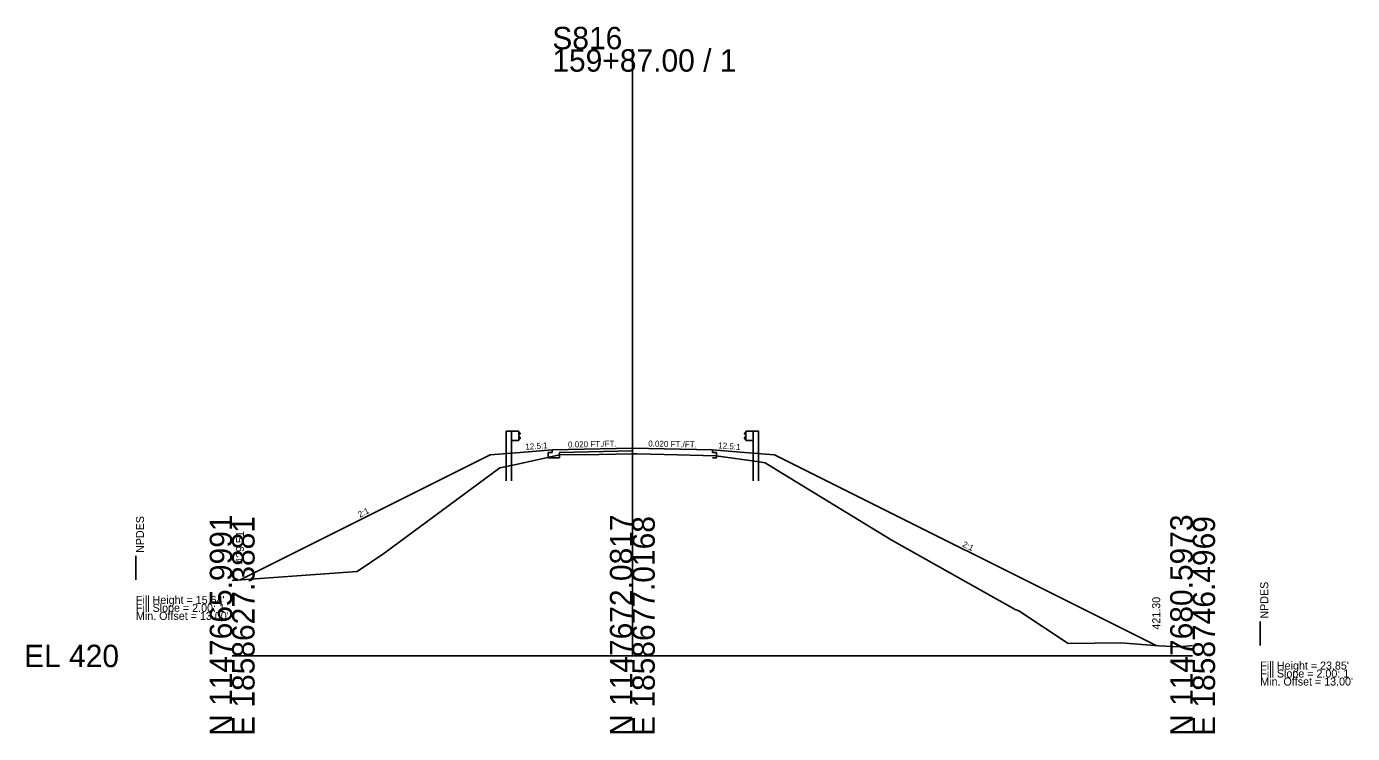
# Model space of a CAD drawing. Extents: x -76 to 4323, y -10 to 2055.
# Drawn here: x 3074.3 to 3240, y -9.7 to 78.7 of the extents above; entities that cross this region are included whole.
import ezdxf

# ---------------------------------------------------------------- set-up
doc = ezdxf.new("R2010")
doc.units = 0
for name, color, linetype in [('Default', 7, 'Continuous'), ('RD_GPK_XS_Cell', 7, 'Continuous'), ('RD_XS_Base', 7, 'Continuous'), ('RD_XS_Buildup', 7, 'Continuous'), ('RD_XS_EarthShd', 7, 'Continuous'), ('RD_XS_ExGround', 7, 'Continuous'), ('RD_XS_GR', 7, 'Continuous'), ('RD_XS_NPDES', 7, 'Continuous'), ('RD_XS_Pave', 7, 'Continuous'), ('RD_XS_TieSlope', 7, 'Continuous'), ('RD_XS_TX_Elev_PR', 7, 'Continuous'), ('RD_XS_TX_ShdSlope', 7, 'Continuous'), ('RD_XS_TX_Slope', 7, 'Continuous'), ('RD_XS_TX_Warning', 7, 'Continuous')]:
    doc.layers.add(name, color=color, linetype=linetype)

msp = doc.modelspace()

# ---------------------------------------------------------------- linework, layer by layer
at = {"layer": 'Default'}
for p, q in [((3140, 25.77), (3150, 25.97)), ((3150, 25.97), (3160, 25.77))]:
    msp.add_line(p, q, dxfattribs=at)
at = {"layer": 'RD_GPK_XS_Cell'}
for p, q in [((3150, 0), (3150, 75.84)), ((3100, 0), (3150, 0)), ((3150, 0), (3220, 0))]:
    msp.add_line(p, q, dxfattribs=at)
at = {"layer": 'RD_XS_Base'}
for p, q in [((3140.89, 24.78), (3140.89, 25.13)), ((3140, 24.77), (3140.89, 24.78))]:
    msp.add_line(p, q, dxfattribs=at)
at = {"layer": 'RD_XS_Buildup'}
for p, q in [((3140.89, 25.45), (3150, 25.64)), ((3140.89, 25.13), (3140.89, 25.45))]:
    msp.add_line(p, q, dxfattribs=at)
at = {"layer": 'RD_XS_EarthShd'}
for p, q in [((3136, 25.45), (3132.25, 25.15)), ((3140, 25.77), (3136, 25.45)), ((3160, 25.77), (3164, 25.45)), ((3164, 25.45), (3167.75, 25.15))]:
    msp.add_line(p, q, dxfattribs=at)
at = {"layer": 'RD_XS_ExGround'}
for p, q in [((3135.49, 23.95), (3140.89, 25.13)), ((3140.89, 25.13), (3145.84, 25.2)), ((3145.84, 25.2), (3150, 25.27)), ((3150, 25.27), (3150.54, 25.28)), ((3150.54, 25.28), (3155.66, 25.14)), ((3155.66, 25.14), (3160.43, 25.01)), ((3160.43, 25.01), (3165.89, 24.26)), ((3118.94, 12.8), (3133.46, 23.52)), ((3133.46, 23.52), (3135.49, 23.95)), ((3165.89, 24.26), (3166.6, 24.16)), ((3166.6, 24.16), (3168.01, 23.28)), ((3168.01, 23.28), (3182.32, 14.5)), ((3182.32, 14.5), (3197.84, 5.79)), ((3115.61, 10.55), (3118.94, 12.8)), ((3100, 9.44), (3115.61, 10.55)), ((3197.84, 5.79), (3198.28, 5.63)), ((3198.28, 5.63), (3204.43, 1.56)), ((3204.43, 1.56), (3211.04, 1.62)), ((3211.04, 1.62), (3215.78, 1.27)), ((3215.78, 1.27), (3218.37, 1.14)), ((3218.37, 1.14), (3220, 1.31))]:
    msp.add_line(p, q, dxfattribs=at)
at = {"layer": 'RD_XS_GR'}
for p, q in [((3134.25, 28.1), (3134.25, 25.31)), ((3134.92, 28.1), (3134.25, 28.1)), ((3134.92, 28.1), (3134.92, 25.36)), ((3135.83, 28.1), (3134.92, 28.1)), ((3135.83, 26.94), (3134.92, 26.94)), ((3135.83, 26.94), (3135.83, 28.1)), ((3135.83, 28.03), (3136, 27.83)), ((3136, 27.78), (3135.83, 27.58)), ((3136, 27.26), (3135.83, 27.46)), ((3135.83, 27.01), (3136, 27.21)), ((3136, 27.83), (3136, 27.78)), ((3136, 27.21), (3136, 27.26)), ((3164.17, 28.03), (3164, 27.83)), ((3164, 27.83), (3164, 27.78)), ((3164, 27.78), (3164.17, 27.58)), ((3164, 27.26), (3164.17, 27.46)), ((3164, 27.21), (3164, 27.26)), ((3164.17, 27.01), (3164, 27.21)), ((3164.17, 26.94), (3164.17, 28.1)), ((3164.17, 28.1), (3165.08, 28.1)), ((3164.17, 26.94), (3165.08, 26.94)), ((3165.08, 28.1), (3165.08, 25.36)), ((3165.08, 28.1), (3165.75, 28.1)), ((3165.75, 28.1), (3165.75, 25.31)), ((3134.25, 25.31), (3134.25, 21.89)), ((3134.92, 21.89), (3134.92, 25.36)), ((3165.08, 21.89), (3165.08, 25.36)), ((3165.75, 25.31), (3165.75, 21.89))]:
    msp.add_line(p, q, dxfattribs=at)
at = {"layer": 'RD_XS_NPDES'}
for p, q in [((3087.98, 9.51), (3087.98, 12.51)), ((3228.45, 1.3), (3228.45, 4.3))]:
    msp.add_line(p, q, dxfattribs=at)
at = {"layer": 'RD_XS_Pave'}
for p, q in [((3139.5, 25.43), (3140, 25.44)), ((3139.5, 24.76), (3139.5, 25.43)), ((3140, 25.44), (3140, 25.77)), ((3160, 25.44), (3160, 25.77)), ((3160.5, 25.43), (3160, 25.44)), ((3160.5, 24.76), (3160.5, 25.43)), ((3140, 24.77), (3139.5, 24.76)), ((3160, 24.77), (3160.5, 24.76))]:
    msp.add_line(p, q, dxfattribs=at)
at = {"layer": 'RD_XS_TieSlope'}
for p, q in [((3132.25, 25.15), (3100.98, 9.51)), ((3167.75, 25.15), (3215.45, 1.3))]:
    msp.add_line(p, q, dxfattribs=at)

# ---------------------------------------------------------------- texts
at = {"layer": 'RD_GPK_XS_Cell'}
for s, p in [('S816', (3140, 75.84)), ('159+87.00 / 1', (3140, 73.04)), ('EL 420', (3074, -1.4))]:
    msp.add_text(s, height=2.8, dxfattribs=at).set_placement(p)
for s, p in [('N 1147665.9991', (3100, -10)), ('E 1858627.3881', (3102.8, -10)), ('N 1147672.0817', (3150, -10)), ('E 1858677.0168', (3152.8, -10)), ('N 1147680.5973', (3220, -10)), ('E 1858746.4969', (3222.8, -10))]:
    msp.add_text(s, height=2.8, rotation=90, dxfattribs=at).set_placement(p)
at = {"layer": 'RD_XS_TX_Elev_PR'}
for s, p in [('429.51', (3101.48, 11.51)), ('421.30', (3215.95, 3.3))]:
    msp.add_text(s, height=1, rotation=90, dxfattribs=at).set_placement(p)
at = {"layer": 'RD_XS_TX_ShdSlope'}
for rotation, p in [(4.5739, (3136.66, 25.75)), (355.4261, (3160.7, 25.96))]:
    msp.add_text('12.5:1', height=0.75, rotation=rotation, dxfattribs=at).set_placement(p)
at = {"layer": 'RD_XS_TX_Slope'}
for s, rotation, p in [('0.020 FT./FT.', 1.1458, (3141.97, 26.05)), ('0.020 FT./FT.', 358.8542, (3151.98, 26.18)), ('2:1', 26.5651, (3115.95, 17.28)), ('2:1', 333.4349, (3191.16, 13.72))]:
    msp.add_text(s, height=0.75, rotation=rotation, dxfattribs=at).set_placement(p)
at = {"layer": 'RD_XS_TX_Warning'}
for p in [(3088.98, 12.51), (3229.45, 4.3)]:
    msp.add_text(' NPDES', height=1, rotation=90, dxfattribs=at).set_placement(p)
for s, p in [("Fill Height = 15.64' ", (3087.98, 6.51)), ('Fill Slope = 2.00: 1', (3087.98, 5.51)), ("Min. Offset = 13.00' ", (3087.98, 4.51)), ("Fill Height = 23.85' ", (3228.45, -1.7)), ('Fill Slope = 2.00: 1', (3228.45, -2.7)), ("Min. Offset = 13.00' ", (3228.45, -3.7))]:
    msp.add_text(s, height=1, dxfattribs=at).set_placement(p)

doc.saveas('drawing.dxf')
